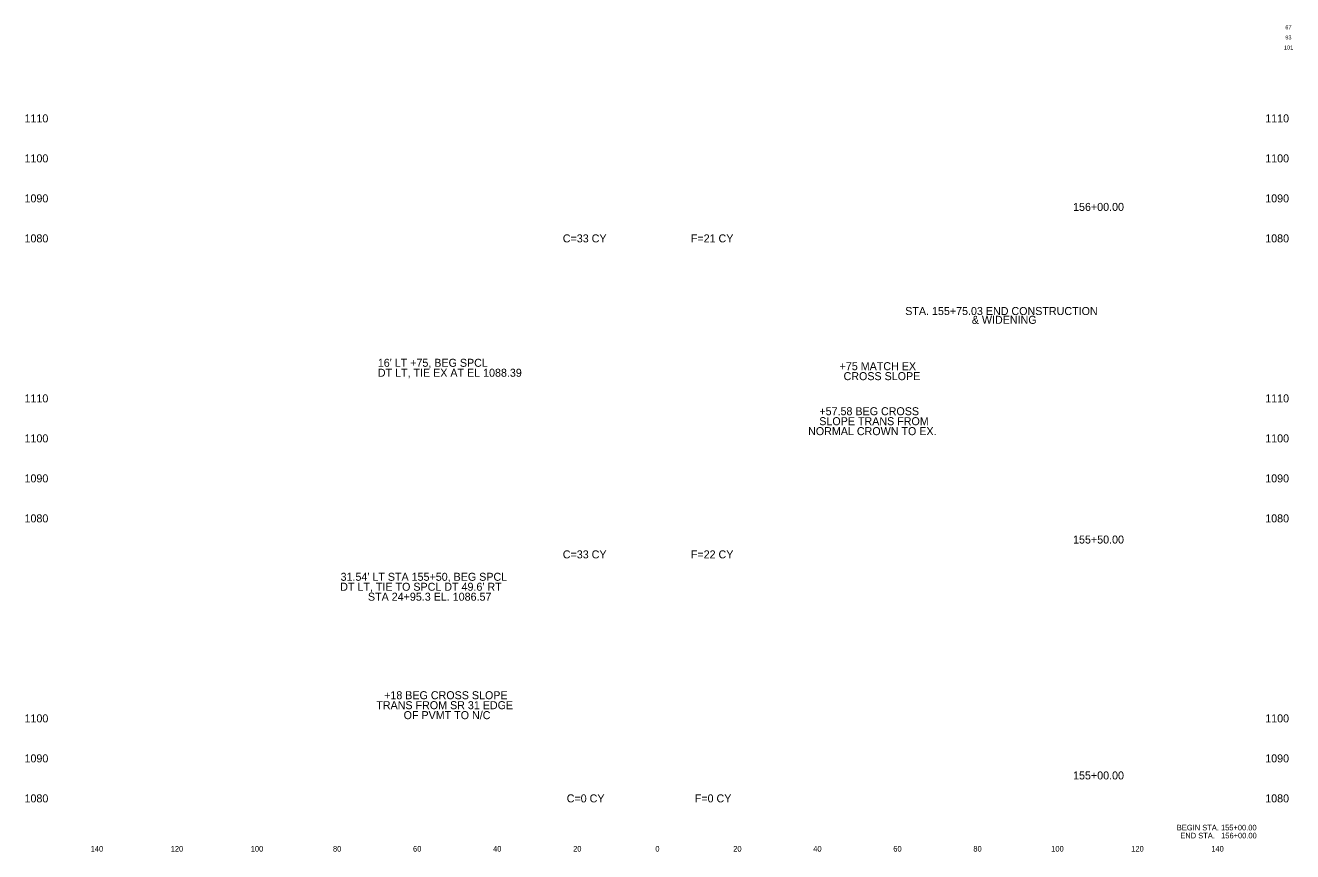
# Model space of a CAD drawing. Extents: x -5 to 1319, y -163 to 1204.
# Drawn here: x 1001.9 to 1318.6, y 997.7 to 1204.3 of the extents above; entities that cross this region are included whole.
import ezdxf

# ---------------------------------------------------------------- set-up
doc = ezdxf.new("R2010")
doc.units = 0
for name, color, linetype in [('Default', 7, 'Continuous'), ('DESIGN - DRAINAGE - Text', 7, 'Continuous'), ('DESIGN - SHEET - Corner Text', 7, 'Continuous'), ('DESIGN - TYPICAL - Finished Grade Slopes Text', 7, 'Continuous'), ('DESIGN - TYPICAL - Text', 7, 'Continuous')]:
    doc.layers.add(name, color=color, linetype=linetype)

msp = doc.modelspace()

# ---------------------------------------------------------------- texts
at = {"layer": 'Default'}
for s, height, p in [('     1110     ', 2, (998.01, 1180)), ('     1110     ', 2, (1308.01, 1180)), ('     1100     ', 2, (998.01, 1170)), ('     1100     ', 2, (1308.01, 1170)), ('     1090     ', 2, (998.01, 1160)), ('     156+00.00     ', 2, (1260, 1157.87)), ('     1090     ', 2, (1308.01, 1160)), ('     1080     ', 2, (998.01, 1150)), ('     1080     ', 2, (1308.01, 1150)), ('STA. 155+75.03 END CONSTRUCTION ', 2, (1221.78, 1131.84)), ('& WIDENING', 2, (1238.41, 1129.64)), ('     1110     ', 2, (998.01, 1110)), ('     1110     ', 2, (1308.01, 1110)), ('     1100     ', 2, (998.01, 1100)), ('     1100     ', 2, (1308.01, 1100)), ('     1090     ', 2, (998.01, 1090)), ('     1090     ', 2, (1308.01, 1090)), ('     1080     ', 2, (998.01, 1080)), ('     1080     ', 2, (1308.01, 1080)), ('     155+50.00     ', 2, (1260, 1074.71)), ('     1100     ', 2, (998.01, 1030)), ('     1100     ', 2, (1308.01, 1030)), ('     1090     ', 2, (998.01, 1020)), ('     1090     ', 2, (1308.01, 1020)), ('     155+00.00     ', 2, (1260, 1015.74)), ('     1080     ', 2, (998.01, 1010)), ('     1080     ', 2, (1308.01, 1010)), ('     140     ', 1.4, (1015.65, 997.7)), ('     120     ', 1.4, (1035.65, 997.7)), ('     100     ', 1.4, (1055.65, 997.7)), ('     80     ', 1.4, (1076.2, 997.7)), ('     60     ', 1.4, (1096.2, 997.7)), ('     40     ', 1.4, (1116.2, 997.7)), ('     20     ', 1.4, (1136.2, 997.7)), ('     0     ', 1.4, (1156.74, 997.7)), ('     0     ', 1.4, (1156.74, 997.7)), ('     20     ', 1.4, (1176.2, 997.7)), ('     40     ', 1.4, (1196.2, 997.7)), ('     60     ', 1.4, (1216.2, 997.7)), ('     80     ', 1.4, (1236.2, 997.7)), ('     100     ', 1.4, (1255.65, 997.7)), ('     120     ', 1.4, (1275.65, 997.7)), ('     140     ', 1.4, (1295.65, 997.7))]:
    msp.add_text(s, height=height, dxfattribs=at).set_placement(p)
at = {"layer": 'DESIGN - DRAINAGE - Text'}
for s, p in [("16' LT +75, BEG SPCL", (1090, 1118.9)), ('DT LT, TIE EX AT EL 1088.39', (1090, 1116.41)), ("31.54' LT STA 155+50, BEG SPCL", (1080.7, 1065.4)), ("DT LT, TIE TO SPCL DT 49.6' RT", (1080.61, 1062.91)), ('STA 24+95.3 EL. 1086.57', (1087.53, 1060.42))]:
    msp.add_text(s, height=2, dxfattribs=at).set_placement(p)
at = {"layer": 'DESIGN - SHEET - Corner Text'}
for s, height, p in [('67', 1, (1316.75, 1203.25)), ('93', 1, (1316.75, 1200.75)), ('101', 1, (1316.41, 1198.22)), ('BEGIN STA. 155+00.00', 1.4, (1289.64, 1003)), ('END STA.   156+00.00', 1.4, (1290.51, 1001))]:
    msp.add_text(s, height=height, dxfattribs=at).set_placement(p)
at = {"layer": 'DESIGN - TYPICAL - Finished Grade Slopes Text'}
for s, p in [('+75 MATCH EX', (1205.38, 1118.05)), ('CROSS SLOPE', (1206.37, 1115.56)), ('+57.58 BEG CROSS ', (1200.33, 1106.79)), ('SLOPE TRANS FROM ', (1200.3, 1104.3)), ('NORMAL CROWN TO EX.', (1197.51, 1101.81)), ('+18 BEG CROSS SLOPE', (1091.58, 1035.79)), ('TRANS FROM SR 31 EDGE', (1089.62, 1033.3)), ('OF PVMT TO N/C', (1096.45, 1030.81))]:
    msp.add_text(s, height=2, dxfattribs=at).set_placement(p)
at = {"layer": 'DESIGN - TYPICAL - Text'}
for s, p in [('C=33 CY', (1136.22, 1150)), ('F=21 CY', (1168.22, 1150)), ('C=33 CY', (1136.22, 1071)), ('F=22 CY', (1168.22, 1071)), ('C=0 CY', (1137.2, 1010)), ('F=0 CY', (1169.2, 1010))]:
    msp.add_text(s, height=2, dxfattribs=at).set_placement(p)

doc.saveas('drawing.dxf')
